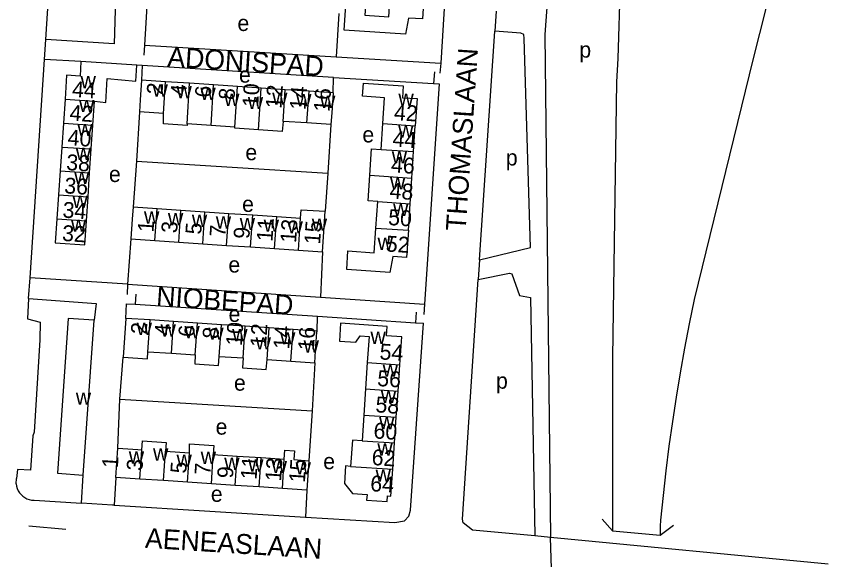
# Model space of a CAD drawing. Extents: x 161773 to 163836, y 384796 to 386521.
# Drawn here: x 162026.8 to 162231.1, y 385740.7 to 385877.5 of the extents above; entities that cross this region are included whole.
import ezdxf

# ---------------------------------------------------------------- set-up
doc = ezdxf.new("R2010")
doc.units = 0
for name, color, linetype in [('BLT_Basislijn', 7, 'Continuous'), ('BLT_Bebouwing', 7, 'Continuous'), ('BLT_Centroide', 7, 'Continuous'), ('BLT_Huisnummer', 7, 'Continuous'), ('BLT_Huisnummer_ tussenligend', 7, 'Continuous'), ('BLT_Onderverdeling_panden', 7, 'Continuous'), ('BLT_Straatnaam', 7, 'Continuous'), ('BLT_Vlakafsluiter', 7, 'Continuous')]:
    doc.layers.add(name, color=color, linetype=linetype)

msp = doc.modelspace()

# ---------------------------------------------------------------- linework, layer by layer
at = {"layer": 'BLT_Basislijn'}
for p, q in [((162137.07, 385920.38), (162133.61, 385865.64)), ((162059.73, 385881.41), (162059.05, 385870.21)), ((162107.93, 385878.16), (162107.3, 385867.25)), ((162147.54, 385878.69), (162147.22, 385873.69)), ((162143.41, 385816.2), (162147.22, 385873.69)), ((162033.83, 385866.61), (162034.19, 385871.62)), ((162059.05, 385870.21), (162058.85, 385867.67)), ((162059.05, 385870.21), (162107.3, 385867.25)), ((162107.3, 385867.25), (162133.61, 385865.64)), ((162030.26, 385811.61), (162033.83, 385866.61)), ((162043.06, 385866.03), (162033.83, 385866.61)), ((162058.43, 385865.06), (162057.12, 385865.14)), ((162058.43, 385865.06), (162058.32, 385861.4)), ((162106.65, 385862.01), (162058.43, 385865.06)), ((162133.61, 385865.64), (162133.41, 385863.11)), ((162212.29, 385866.81), (162197.43, 385806.17)), ((162132.06, 385863.47), (162131.82, 385860.5)), ((162106.53, 385858.16), (162106.65, 385862.01)), ((162106.65, 385862.01), (162131.82, 385860.5)), ((162177.9, 385860.98), (162176.88, 385791.59)), ((162133.2, 385860.42), (162129.52, 385805.05)), ((162131.82, 385860.5), (162133.2, 385860.42)), ((162057.79, 385853.43), (162057.01, 385840.98)), ((162105.99, 385850.19), (162105.19, 385838.01)), ((162057.01, 385840.98), (162056.18, 385829.49)), ((162057.01, 385840.98), (162105.19, 385838.01)), ((162105.19, 385838.01), (162104.51, 385828.4)), ((162055.64, 385821.44), (162054.8, 385810.04)), ((162103.83, 385818.2), (162103.35, 385806.78)), ((162143.41, 385816.2), (162143.02, 385811.24)), ((162029.88, 385806.48), (162030.26, 385811.61)), ((162054.8, 385810.04), (162030.26, 385811.61)), ((162054.8, 385810.04), (162054.65, 385807.42)), ((162054.8, 385810.04), (162103.35, 385806.78)), ((162056.85, 385807.53), (162056.71, 385805)), ((162103.35, 385806.78), (162129.52, 385805.05)), ((162056.71, 385805), (162102.57, 385801.99)), ((162129.52, 385805.05), (162129.37, 385802.43)), ((162102.48, 385798.27), (162102.57, 385801.99)), ((162102.57, 385801.99), (162127.3, 385800.35)), ((162127.44, 385802.97), (162127.3, 385800.35)), ((162127.3, 385800.35), (162129.25, 385800.22)), ((162052.86, 385781.14), (162053.67, 385791.68)), ((162176.88, 385791.59), (162176.88, 385748)), ((162101.93, 385790.29), (162101.24, 385778.22)), ((162052.34, 385768.82), (162052.86, 385781.14)), ((162052.86, 385781.14), (162101.24, 385778.22)), ((162101.24, 385778.22), (162100.4, 385765.62)), ((162026.76, 385759.79), (162026.85, 385761.13)), ((162043.22, 385754.99), (162043.64, 385762.02)), ((162051.85, 385761.43), (162051.42, 385754.45)), ((162099.91, 385758.24), (162099.62, 385751.45)), ((162031.3, 385755.7), (162043.22, 385754.99)), ((162051.42, 385754.45), (162099.62, 385751.45)), ((162174.26, 385750.92), (162176.88, 385748)), ((162029.92, 385749.3), (162039.26, 385748.41)), ((162188.83, 385746.9), (162192.18, 385749.46)), ((162188.83, 385749.17), (162188.83, 385746.9)), ((162161.24, 385746.35), (162157.32, 385746.74)), ((162176.88, 385748), (162188.83, 385746.9)), ((162231.14, 385739.66), (162161.24, 385746.35))]:
    msp.add_line(p, q, dxfattribs=at)
for points in [[(162222.66, 386076.72), (162222.42, 386075.78), (162221.94, 386075.27), (162220.69, 386070.17), (162216.01, 386049.98), (162197.07, 385972.43), (162167.75, 385940.71), (162164.04, 385930.05), (162159.87, 385872.82), (162161.24, 385746.35)], [(162182.56, 385940.86), (162180.52, 385915.35), (162178.77, 385886.05), (162178.19, 385866.81), (162177.9, 385860.98)], [(162034.19, 385871.62), (162034.89, 385882.19), (162038.52, 385882.21), (162038.88, 385886.32), (162040.81, 385921.26), (162037.64, 385921.55), (162037.86, 385926.6)], [(162226.57, 385926.28), (162224.38, 385915.21), (162220.16, 385898), (162212.29, 385866.81)], [(162051.78, 385881.91), (162051.45, 385870.49), (162034.19, 385871.62)], [(162143.41, 385816.2), (162156.18, 385819.3), (162154.66, 385871.87), (162154.52, 385872.85), (162153.82, 385873.22), (162147.22, 385873.69)], [(162143.02, 385811.24), (162150.96, 385812.82), (162151.5, 385812.69), (162153.44, 385807.21), (162156.26, 385806.74), (162157.32, 385746.74)], [(162157.32, 385746.74), (162141.59, 385748.16), (162139.31, 385750.05), (162139.1, 385750.93), (162143.02, 385811.24)], [(162029.88, 385806.48), (162029.56, 385801.36), (162032.82, 385800.53), (162032.68, 385796.06), (162031.26, 385772.84), (162030.96, 385771.91), (162030.37, 385763.26), (162027.11, 385763.44), (162026.85, 385761.13)], [(162029.88, 385806.48), (162046.84, 385805.18), (162046.39, 385800.97)], [(162197.43, 385806.17), (162196.17, 385800.06), (162194.99, 385793.93), (162193.9, 385787.79), (162192.88, 385781.64), (162191.94, 385775.48), (162191.08, 385769.3), (162190.3, 385763.11), (162189.6, 385756.92), (162188.97, 385750.71), (162188.83, 385749.17)], [(162054.32, 385801.46), (162054.48, 385805.14), (162056.71, 385805)], [(162099.62, 385751.45), (162122.07, 385750.08), (162124.52, 385750.49), (162125.56, 385751.7), (162125.99, 385753.18), (162129.25, 385800.22)], [(162026.76, 385759.79), (162026.85, 385759.2), (162027.02, 385758.62), (162027.27, 385758.08), (162027.59, 385757.57), (162027.97, 385757.11), (162028.41, 385756.7), (162028.9, 385756.35), (162029.44, 385756.08), (162030, 385755.87), (162030.59, 385755.74), (162031.19, 385755.7), (162031.3, 385755.7)], [(162051.42, 385754.45), (162050.98, 385754.48), (162043.22, 385754.99)]]:
    msp.add_lwpolyline(points, dxfattribs=at)
at = {"layer": 'BLT_Bebouwing'}
for p, q in [((162057.12, 385865.14), (162043.06, 385866.03)), ((162064.35, 385860.99), (162058.32, 385861.4)), ((162070.37, 385860.59), (162064.35, 385860.99)), ((162076.4, 385860.19), (162070.37, 385860.59)), ((162082.42, 385859.78), (162076.4, 385860.19)), ((162088.44, 385859.38), (162082.42, 385859.78)), ((162094.47, 385858.97), (162088.44, 385859.38)), ((162100.49, 385858.57), (162094.47, 385858.97)), ((162106.53, 385858.16), (162100.49, 385858.57)), ((162039.04, 385856.6), (162038.63, 385850.58)), ((162046.06, 385850.08), (162046.46, 385856.1)), ((162063.81, 385853.02), (162057.79, 385853.43)), ((162038.63, 385850.58), (162038.22, 385844.56)), ((162099.95, 385850.6), (162093.93, 385851)), ((162105.99, 385850.19), (162099.95, 385850.6)), ((162045.65, 385844.06), (162046.06, 385850.08)), ((162075.79, 385849.99), (162069.82, 385850.39)), ((162118.61, 385843.95), (162119.05, 385850.44)), ((162126.8, 385843.41), (162127.2, 385849.9)), ((162038.22, 385844.56), (162037.81, 385838.54)), ((162045.24, 385838.04), (162045.65, 385844.06)), ((162126.35, 385836.75), (162126.8, 385843.41)), ((162037.81, 385838.54), (162037.4, 385832.52)), ((162044.83, 385832.02), (162045.24, 385838.04)), ((162125.94, 385830.27), (162126.35, 385836.75)), ((162037.4, 385832.52), (162037, 385826.5)), ((162044.43, 385826), (162044.83, 385832.02)), ((162117.32, 385824.12), (162117.77, 385830.81)), ((162125.49, 385823.6), (162125.94, 385830.27)), ((162056.18, 385829.49), (162062.2, 385829.09)), ((162062.2, 385829.09), (162068.23, 385828.68)), ((162068.23, 385828.68), (162074.25, 385828.28)), ((162074.25, 385828.28), (162080.27, 385827.87)), ((162080.27, 385827.87), (162086.3, 385827.47)), ((162086.3, 385827.47), (162092.32, 385827.06)), ((162092.32, 385827.06), (162098.35, 385826.66)), ((162055.64, 385821.44), (162061.66, 385821.04)), ((162061.66, 385821.04), (162067.69, 385820.63)), ((162067.69, 385820.63), (162073.71, 385820.23)), ((162073.71, 385820.23), (162079.73, 385819.82)), ((162079.73, 385819.82), (162085.76, 385819.42)), ((162085.76, 385819.42), (162091.78, 385819.01)), ((162091.78, 385819.01), (162097.81, 385818.61)), ((162097.81, 385818.61), (162103.83, 385818.2)), ((162043.64, 385762.02), (162046.39, 385800.97)), ((162054.32, 385801.46), (162053.67, 385791.68)), ((162060.45, 385801.05), (162054.32, 385801.46)), ((162066.35, 385800.66), (162060.45, 385801.05)), ((162072.37, 385800.26), (162066.35, 385800.66)), ((162078.39, 385799.86), (162072.37, 385800.26)), ((162084.4, 385799.46), (162078.39, 385799.86)), ((162090.42, 385799.06), (162084.4, 385799.46)), ((162096.44, 385798.66), (162090.42, 385799.06)), ((162102.48, 385798.27), (162096.44, 385798.66)), ((162059.92, 385793.07), (162065.82, 385792.68)), ((162065.82, 385792.68), (162071.84, 385792.29)), ((162077.86, 385791.89), (162083.88, 385791.49)), ((162089.9, 385791.09), (162095.91, 385790.69)), ((162115.12, 385790.33), (162114.68, 385783.73)), ((162122.87, 385783.18), (162123.31, 385789.78)), ((162114.68, 385783.73), (162114.24, 385777.12)), ((162122.42, 385776.57), (162122.87, 385783.18)), ((162114.24, 385777.12), (162113.81, 385770.67)), ((162121.99, 385770.12), (162122.42, 385776.57)), ((162121.54, 385763.51), (162121.99, 385770.12)), ((162051.85, 385761.43), (162052.34, 385768.82)), ((162064.35, 385768.02), (162070.36, 385767.62)), ((162076.37, 385767.22), (162082.38, 385766.82)), ((162082.38, 385766.82), (162088.39, 385766.42)), ((162088.39, 385766.42), (162094.24, 385766.03)), ((162057.85, 385761.03), (162051.85, 385761.43)), ((162063.86, 385760.63), (162057.85, 385761.03)), ((162069.87, 385760.24), (162063.86, 385760.63)), ((162075.88, 385759.84), (162069.87, 385760.24)), ((162081.89, 385759.44), (162075.88, 385759.84)), ((162087.89, 385759.04), (162081.89, 385759.44)), ((162093.79, 385758.64), (162087.89, 385759.04)), ((162099.91, 385758.24), (162093.79, 385758.64))]:
    msp.add_line(p, q, dxfattribs=at)
for points in [[(162129.46, 385883.39), (162129.02, 385876.76), (162125.49, 385876.99), (162124.76, 385872.95), (162109.28, 385873.98), (162109.62, 385878.97), (162109.99, 385884.62), (162114.98, 385884.29), (162114.54, 385877.7), (162120.54, 385877.3), (162120.99, 385883.96)], [(162043.06, 385866.03), (162042.82, 385862.39), (162039.44, 385862.62), (162039.04, 385856.6)], [(162046.46, 385856.1), (162049.3, 385855.78), (162049.61, 385861.79), (162056.85, 385861.11), (162057.12, 385865.14)], [(162058.32, 385861.4), (162057.99, 385856.41), (162057.79, 385853.43)], [(162119.05, 385850.44), (162119.49, 385856.94), (162113.92, 385857.31), (162114.14, 385860.63), (162124.2, 385859.95), (162124, 385856.97), (162127.66, 385856.72), (162127.2, 385849.9)], [(162106.53, 385858.16), (162106.19, 385853.17), (162105.99, 385850.19)], [(162069.82, 385850.39), (162069.79, 385849.99), (162063.84, 385850.37), (162063.81, 385853.02)], [(162093.93, 385851), (162093.73, 385848.44), (162087.75, 385848.85)], [(162081.77, 385849.59), (162075.79, 385849.99)], [(162087.75, 385848.85), (162081.75, 385849.26), (162081.77, 385849.59)], [(162115.79, 385837.46), (162116.23, 385844.06), (162118.61, 385843.95)], [(162117.77, 385830.81), (162115.35, 385830.98), (162115.79, 385837.46)], [(162056.18, 385829.49), (162055.97, 385826.43), (162055.64, 385821.44)], [(162098.35, 385826.66), (162098.51, 385828.77), (162104.51, 385828.4)], [(162103.83, 385818.2), (162104.16, 385823.19), (162104.51, 385828.4)], [(162037, 385826.5), (162036.59, 385820.47), (162044.02, 385819.97), (162044.43, 385826)], [(162125.49, 385823.6), (162125.02, 385816.78), (162121.54, 385817.02), (162120.84, 385813.01), (162109.96, 385813.74), (162110.27, 385818.41), (162116.9, 385817.96), (162117.32, 385824.12)], [(162046.39, 385800.97), (162039.87, 385801.43), (162037.12, 385762.48), (162043.64, 385762.02)], [(162123.31, 385789.78), (162123.79, 385796.79), (162119.95, 385797.05), (162120.11, 385799.44), (162108.4, 385800.23), (162108.1, 385795.73), (162112.25, 385795.45), (162113.35, 385797.08), (162115.57, 385796.93), (162115.12, 385790.33)], [(162101.93, 385790.29), (162102.12, 385793.28), (162102.43, 385797.95), (162102.48, 385798.27)], [(162053.67, 385791.68), (162059.8, 385791.27), (162059.92, 385793.07)], [(162071.84, 385792.29), (162071.73, 385790.02), (162077.71, 385789.63), (162077.86, 385791.89)], [(162083.88, 385791.49), (162083.69, 385788.97), (162089.66, 385788.57), (162089.9, 385791.09)], [(162095.91, 385790.69), (162101.93, 385790.29)], [(162058.35, 385768.42), (162058.51, 385770.68), (162064.51, 385770.26), (162064.35, 385768.02)], [(162070.36, 385767.62), (162070.41, 385769.87), (162076.52, 385769.46), (162076.37, 385767.22)], [(162113.81, 385770.67), (162111.37, 385770.83), (162110.92, 385764.22)], [(162052.34, 385768.82), (162057.33, 385768.49), (162058.35, 385768.42)], [(162094.24, 385766.03), (162094.39, 385768.28), (162096.83, 385768.11), (162096.68, 385765.98), (162100.4, 385765.62)], [(162100.4, 385765.62), (162100.24, 385763.23), (162099.91, 385758.24)], [(162110.92, 385764.22), (162109.67, 385764.32), (162109.37, 385759.88), (162111.44, 385757.41), (162115.07, 385757.16), (162114.97, 385755.72), (162120.14, 385755.38), (162120.24, 385756.81), (162121.09, 385756.75), (162121.54, 385763.51)]]:
    msp.add_lwpolyline(points, dxfattribs=at)
at = {"layer": 'BLT_Onderverdeling_panden'}
for p, q in [((162063.81, 385853.02), (162064.35, 385860.99)), ((162069.82, 385850.39), (162070.37, 385860.59)), ((162075.79, 385849.99), (162076.4, 385860.19)), ((162081.77, 385849.59), (162082.42, 385859.78)), ((162087.75, 385848.85), (162088.44, 385859.38)), ((162093.93, 385851), (162094.47, 385858.97)), ((162099.95, 385850.6), (162100.49, 385858.57)), ((162039.04, 385856.6), (162046.46, 385856.1)), ((162038.63, 385850.58), (162046.06, 385850.08)), ((162119.05, 385850.44), (162127.2, 385849.9)), ((162038.22, 385844.56), (162045.65, 385844.06)), ((162118.61, 385843.95), (162126.8, 385843.41)), ((162037.81, 385838.54), (162045.24, 385838.04)), ((162115.79, 385837.46), (162126.35, 385836.75)), ((162037.4, 385832.52), (162044.83, 385832.02)), ((162117.77, 385830.81), (162125.94, 385830.27)), ((162061.66, 385821.04), (162062.2, 385829.09)), ((162067.69, 385820.63), (162068.23, 385828.68)), ((162073.71, 385820.23), (162074.25, 385828.28)), ((162037, 385826.5), (162044.43, 385826)), ((162079.73, 385819.82), (162080.27, 385827.87)), ((162085.76, 385819.42), (162086.3, 385827.47)), ((162091.78, 385819.01), (162092.32, 385827.06)), ((162097.81, 385818.61), (162098.35, 385826.66)), ((162117.32, 385824.12), (162125.49, 385823.6)), ((162059.92, 385793.07), (162060.45, 385801.05)), ((162065.82, 385792.68), (162066.35, 385800.66)), ((162071.84, 385792.29), (162072.37, 385800.26)), ((162077.86, 385791.89), (162078.39, 385799.86)), ((162083.88, 385791.49), (162084.4, 385799.46)), ((162089.9, 385791.09), (162090.42, 385799.06)), ((162095.91, 385790.69), (162096.44, 385798.66)), ((162115.12, 385790.33), (162123.31, 385789.78)), ((162114.68, 385783.73), (162122.87, 385783.18)), ((162114.24, 385777.12), (162122.42, 385776.57)), ((162113.81, 385770.67), (162121.99, 385770.12)), ((162057.85, 385761.03), (162058.35, 385768.42)), ((162063.86, 385760.63), (162064.35, 385768.02)), ((162069.87, 385760.24), (162070.36, 385767.62)), ((162075.88, 385759.84), (162076.37, 385767.22)), ((162081.89, 385759.44), (162082.38, 385766.82)), ((162087.89, 385759.04), (162088.39, 385766.42)), ((162093.79, 385758.64), (162094.24, 385766.03)), ((162110.92, 385764.22), (162121.54, 385763.51))]:
    msp.add_line(p, q, dxfattribs=at)
at = {"layer": 'BLT_Vlakafsluiter'}
msp.add_line((162161.76, 385730.39), (162161.24, 385746.35), dxfattribs=at)

# ---------------------------------------------------------------- texts
at = {"layer": 'BLT_Centroide'}
for s, p in [('e', (162082.45, 385873.74)), ('p', (162168.51, 385867.04)), ('e', (162082.84, 385860.75)), ('w', (162042.95, 385859.34)), ('w', (162061.06, 385857.22)), ('w', (162067.09, 385856.81)), ('w', (162073.11, 385856.41)), ('w', (162079.08, 385854.88)), ('w', (162085.06, 385854.09)), ('w', (162091.19, 385855.19)), ('w', (162097.2, 385854.78)), ('w', (162103.23, 385854.38)), ('w', (162122.97, 385854.89)), ('w', (162042.55, 385853.34)), ('w', (162042.14, 385847.31)), ('e', (162113.9, 385845.71)), ('w', (162122.91, 385846.94)), ('w', (162041.73, 385841.31)), ('e', (162084.44, 385841.24)), ('w', (162121.29, 385840.41)), ('p', (162150.01, 385839.9)), ('w', (162041.32, 385835.28)), ('e', (162050.1, 385835.75)), ('w', (162120.86, 385833.88)), ('w', (162040.91, 385829.25)), ('e', (162083.62, 385828.23)), ('w', (162121.63, 385827.22)), ('w', (162058.92, 385825.27)), ('w', (162040.51, 385823.25)), ('w', (162064.94, 385824.86)), ('w', (162070.97, 385824.45)), ('w', (162077, 385824.05)), ('w', (162083.02, 385823.64)), ('w', (162089.05, 385823.23)), ('w', (162101.16, 385823.48)), ('w', (162095.06, 385822.83)), ('w', (162117.72, 385818.66)), ('e', (162080.17, 385812.98)), ('e', (162080.21, 385800.57)), ('w', (162057.06, 385797.27)), ('w', (162063.08, 385796.88)), ('w', (162069.09, 385796.47)), ('w', (162075.11, 385796.06)), ('w', (162081.12, 385795.67)), ('w', (162093.17, 385794.88)), ('w', (162115.94, 385795)), ('w', (162087.03, 385793.62)), ('w', (162099.11, 385792.84)), ('w', (162119, 385786.75)), ('e', (162081.57, 385783.26)), ('p', (162147.54, 385783.76)), ('w', (162118.55, 385780.16)), ('w', (162041.75, 385779.72)), ('e', (162076.95, 385772.2)), ('w', (162118.11, 385773.53)), ('w', (162117.66, 385766.94)), ('w', (162055.09, 385764.92)), ('w', (162061.19, 385765.66)), ('w', (162067.11, 385764.12)), ('w', (162073.19, 385764.84)), ('w', (162079.12, 385763.33)), ('w', (162085.14, 385762.92)), ('w', (162091.06, 385762.53)), ('w', (162097.09, 385762.19)), ('e', (162104.04, 385763.51)), ('w', (162117.22, 385760.34)), ('e', (162075.75, 385755.3))]:
    msp.add_text(s, height=4, dxfattribs=at).set_placement(p)
at = {"layer": 'BLT_Huisnummer'}
for s, rotation, p in [('44', 356.126, (162040.72, 385857.18)), ('2', 86.1459, (162063.57, 385857.64)), ('6', 86.1463, (162075.72, 385856.9)), ('10', 86.1473, (162087.65, 385854.5)), ('16', 86.1577, (162105.63, 385853.32)), ('42', 356.2074, (162121.77, 385851.35)), ('40', 356.1255, (162039.61, 385845.02)), ('46', 356.2078, (162121.02, 385838.2)), ('36', 356.125, (162038.77, 385832.93)), ('32', 356.126, (162038.22, 385820.96)), ('1', 86.1552, (162061.3, 385823.01)), ('5', 86.1543, (162073.31, 385822.46)), ('9', 86.1533, (162085.43, 385821.35)), ('15', 86.1585, (162103.24, 385819.98)), ('52', 356.1564, (162119.7, 385818.3)), ('2', 86.2112, (162059.58, 385797.34)), ('6', 86.2107, (162071.54, 385796.66)), ('10', 86.2098, (162083.54, 385794.44)), ('16', 86.2149, (162101.68, 385793.26)), ('54', 356.1562, (162118.14, 385791.14)), ('58', 356.1539, (162117.1, 385777.84)), ('1', 86.1972, (162052.33, 385763.71)), ('5', 86.1962, (162069.53, 385762.34)), ('15', 86.1928, (162099.42, 385760.04)), ('9', 86.1957, (162081.3, 385761.12)), ('64', 356.1464, (162115.79, 385758))]:
    msp.add_text(s, height=4, rotation=rotation, dxfattribs=at).set_placement(p)
at = {"layer": 'BLT_Huisnummer_ tussenligend'}
for s, rotation, p in [('4', 86.1459, (162069.54, 385857.27)), ('8', 86.1463, (162081.69, 385856.31)), ('12', 86.1473, (162093.51, 385854.15)), ('14', 86.1473, (162099.59, 385853.78)), ('42', 356.1255, (162040.1, 385851.23)), ('44', 356.2074, (162121.4, 385844.67)), ('38', 356.125, (162039.26, 385838.78)), ('48', 356.2078, (162120.67, 385831.64)), ('34', 356.126, (162038.33, 385826.81)), ('50', 356.2078, (162120.3, 385824.95)), ('11', 86.1533, (162091.25, 385820.69)), ('13', 86.1533, (162097.19, 385820.36)), ('3', 86.1552, (162067.24, 385822.8)), ('7', 86.1543, (162079.4, 385821.85)), ('4', 86.2112, (162065.55, 385796.97)), ('12', 86.2098, (162089.63, 385794.09)), ('8', 86.2107, (162077.63, 385796.19)), ('14', 86.2098, (162095.48, 385793.6)), ('56', 356.1562, (162117.55, 385784.45)), ('60', 356.1539, (162116.61, 385771.27)), ('62', 356.1539, (162116.15, 385764.58)), ('3', 86.1972, (162058.51, 385763.02)), ('7', 86.1962, (162075.62, 385761.97)), ('11', 86.1957, (162087.25, 385760.82)), ('13', 86.1957, (162093.42, 385760.37))]:
    msp.add_text(s, height=4, rotation=rotation, dxfattribs=at).set_placement(p)
at = {"layer": 'BLT_Straatnaam'}
for s, rotation, p in [('ADONISPAD', 356.3692, (162064.71, 385864.83)), ('THOMASLAAN', 86.1083, (162139.88, 385823.32)), ('NIOBEPAD', 356.1407, (162061.89, 385804.6)), ('AENEASLAAN', 356.4202, (162059.09, 385743.75))]:
    msp.add_text(s, height=5, rotation=rotation, dxfattribs=at).set_placement(p)

doc.saveas('drawing.dxf')
